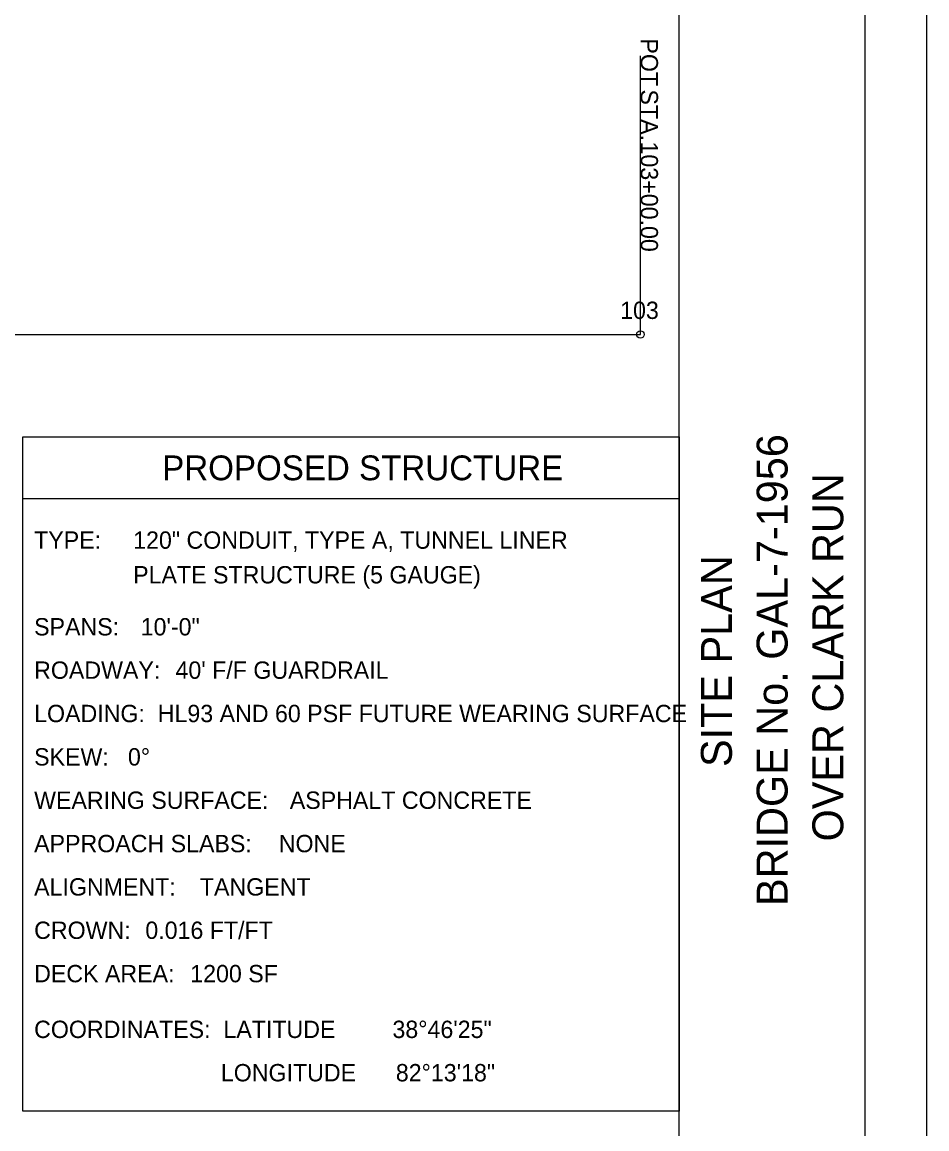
# Model space of a CAD drawing. Extents: x 0 to 2360, y -10 to 232.
# Drawn here: x 266.9 to 340, y 85.4 to 174.8 of the extents above; entities that cross this region are included whole.
import ezdxf

# ---------------------------------------------------------------- set-up
doc = ezdxf.new("R2010")
doc.units = 0
for name, color, linetype in [('_CIVIL_CONSTRUCTION', 7, 'Continuous'), ('BR_P_Brg_Centerline', 7, 'Continuous'), ('BR_P_Sub_Backwall', 7, 'Continuous'), ('DR_P_Culvert', 7, 'Continuous'), ('MT_P_Text', 7, 'Continuous'), ('TX_P_1', 7, 'Continuous')]:
    doc.layers.add(name, color=color, linetype=linetype)

msp = doc.modelspace()

# ---------------------------------------------------------------- linework, layer by layer
at = {"layer": '_CIVIL_CONSTRUCTION'}
msp.add_line((16.859, 149.564), (316.859, 149.564), dxfattribs=at)
at = {"layer": 'BR_P_Brg_Centerline'}
msp.add_lwpolyline([(0, 0), (340, 0), (340, 220), (0, 220)], close=True, dxfattribs=at)
at = {"layer": 'BR_P_Sub_Backwall'}
for p, q in [((266.973, 141.293), (320, 141.293)), ((266.973, 86.843), (266.973, 141.293)), ((320, 141.293), (320, 86.843)), ((320, 136.293), (266.973, 136.293)), ((320, 86.843), (266.973, 86.843))]:
    msp.add_line(p, q, dxfattribs=at)
at = {"layer": 'DR_P_Culvert'}
msp.add_line((316.859, 149.564), (316.859, 172.064), dxfattribs=at)
msp.add_circle((316.859, 149.564), 0.3, dxfattribs=at)
at = {"layer": 'MT_P_Text'}
msp.add_line((316.859, 149.564), (316.859, 150.564), dxfattribs=at)
at = {"layer": 'TX_P_1'}
msp.add_line((320, 5), (320, 215), dxfattribs=at)
msp.add_lwpolyline([(15, 215), (335, 215), (335, 5), (15, 5)], close=True, dxfattribs=at)

# ---------------------------------------------------------------- texts
at = {"layer": 'BR_P_Sub_Backwall'}
for s, p in [('BRIDGE No. GAL-7-1956', (328.75, 103.423)), ('OVER CLARK RUN', (333.25, 108.633)), ('SITE PLAN', (324.25, 114.642))]:
    msp.add_text(s, height=2.5, rotation=90, dxfattribs=at).set_placement(p)
for s, height, p in [('PROPOSED STRUCTURE', 2, (278.23, 137.793)), ('TYPE:', 1.4, (267.886, 132.262)), ('120" CONDUIT, TYPE A, TUNNEL LINER', 1.4, (275.886, 132.262)), ('PLATE STRUCTURE (5 GAUGE)', 1.4, (275.886, 129.462)), ('SPANS:', 1.4, (267.886, 125.262)), ('10\'-0"', 1.4, (276.494, 125.262)), ('ROADWAY:', 1.4, (267.886, 121.762)), ("40' F/F GUARDRAIL", 1.4, (279.306, 121.762)), ('LOADING:  HL93 AND 60 PSF FUTURE WEARING SURFACE', 1.4, (267.886, 118.262)), ('SKEW:', 1.4, (267.886, 114.762)), ('0°', 1.4, (275.463, 114.762)), ('WEARING SURFACE:', 1.4, (267.886, 111.262)), ('ASPHALT CONCRETE', 1.4, (288.539, 111.262)), ('APPROACH SLABS:', 1.4, (267.886, 107.762)), ('NONE', 1.4, (287.647, 107.762)), ('ALIGNMENT:', 1.4, (267.886, 104.262)), ('TANGENT', 1.4, (281.274, 104.262)), ('CROWN:', 1.4, (267.886, 100.762)), ('0.016 FT/FT', 1.4, (276.869, 100.762)), ('DECK AREA:', 1.4, (267.886, 97.262)), ('1200 SF', 1.4, (280.497, 97.262)), ('COORDINATES:  LATITUDE', 1.4, (267.886, 92.762)), ('38°46\'25"', 1.4, (296.831, 92.762)), ('                             LONGITUDE', 1.4, (267.886, 89.262)), ('82°13\'18"', 1.4, (297.104, 89.262))]:
    msp.add_text(s, height=height, dxfattribs=at).set_placement(p)
at = {"layer": 'DR_P_Culvert'}
for s, p in [('POT', (316.881, 173.464)), (' STA. ', (316.881, 169.863)), ('103+00.00', (316.881, 165.138))]:
    msp.add_text(s, height=1.4, rotation=270, dxfattribs=at).set_placement(p)
at = {"layer": 'MT_P_Text'}
msp.add_text('103', height=1.4, rotation=360, dxfattribs=at).set_placement((315.224, 150.814))

doc.saveas('drawing.dxf')
